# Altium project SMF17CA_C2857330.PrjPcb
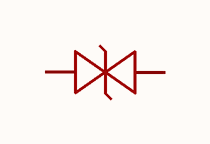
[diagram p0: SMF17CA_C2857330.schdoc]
1 sheet, 1 parts. Net scope: global (net labels, ports and power ports of the same name join across sheets).

## Sheet SMF17CA_C2857330.schdoc
size 127 x 101 mm

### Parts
D?  smf17ca_c2857330  [SMF_L2.9-W1.9-LS3.9-BI]  (value not drawn)

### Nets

Not connected (* = marked no-connect by the designer): D? 1(C) 2(A)

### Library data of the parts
D? = smf17ca_c2857330: 极性:双向;反向截止电压(Vrwm):17V;钳位电压:27.6V;峰值脉冲电流(Ipp):7.2A;峰值脉冲功率(Ppp):200W@10/1000us;击穿电压(VBR):18.9V;; Manufacturer: JSMSEMI(杰盛微); AddInBom: yes; ModelId: 9b190ad72b2a4f2384918ea07687d3cf; ModelName: DO-219AB_L2.8-W1.8-H1.0-LS3.7; ModelTransform: 145.669,70.866,0,0,0,0,0,0,0; Polarity: 双向; Reverse Stand-Off Voltage (Vrwm): 17V; Clamping Voltage: 27.6V; Peak Pulse Current (Ipp): 7.2A; Voltage - Breakdown: 18.9V; Reverse Leakage Current (Ir): 1uA; Number of Channels: 单路; Type: TVS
